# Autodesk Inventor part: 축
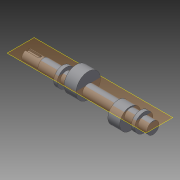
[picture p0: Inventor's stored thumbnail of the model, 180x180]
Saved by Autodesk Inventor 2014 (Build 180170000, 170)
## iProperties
Created: 2014-12
Part Number: 축
Material: 일반
Document SubType Name: Modeling
Designer: Owner
Density: 1 g/cm^3
Appearance: 기본값
Author: Owner
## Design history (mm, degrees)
sketch "스케치1"
  geometry: L1 (-90, 0)-(90, 0); L2 (-90, 0)-(-90, 7.5); L3 (-90, 7.5)-(-66, 7.5); L4 (-66, 7.5)-(-66, 8.5); L5 (-66, 8.5)-(-39, 8.5); L6 (-39, 8.5)-(-39, 13); L7 (-39, 13)-(-34, 13); L8 (-34, 13)-(-34, 8.5); L9 (-34, 8.5)-(72, 8.5); L10 (72, 8.5)-(72, 13); L11 (72, 13)-(77, 13); L12 (77, 13)-(77, 8.5); L13 (77, 8.5)-(90, 8.5); L14 (90, 8.5)-(90, 0); 7 further points
  constraints: 28 end point, 6 midpoint, 6 parallel, 4 perpendicular, 3 collinear, 3 horizontal alignment, 2 horizontal, 1 coincident
  dimensions: "d0" = 180 distance of L1.start L1.end; "d1" = 15 diameter of L3 L1; "d2" = 24 distance between parallel lines of L4 L2; "d3" = 32 distance between parallel lines of L4 L8; "d4" = 5 distance of L6.end L7.end; "d5" = 26 diameter of L7 L1; "d6" = 17 diameter of L5 L1; "d7" = 13 distance between parallel lines of L14 L12
revolve "회전1" sketch "스케치1" stored, may be unused: angle "d8" = 90 deg
node "작업 평면1"
sketch "스케치2"
  geometry: C1 r 17.5 at (-6, 0); 1 further point
  constraints: 1 centre point, 1 horizontal alignment
  dimensions: "d10" = 35 diameter of C1; "d11" = 6 distance of point (0, 0) C1.centre
extrude "돌출1" join sketch "스케치2" distance "d12" = 17; taper "d13" = 0 deg
node "작업 평면2"
sketch "스케치3"
  geometry: C1 r 15 at (-5, 0); 1 further point
  constraints: 1 centre point, 1 horizontal alignment
  dimensions: "d15" = 30 diameter of C1; "d16" = 5 distance of C1.centre point (0, 0)
extrude "돌출2" join sketch "스케치3" distance "d17" = 17; taper "d18" = 0 deg
node "작업 평면3"
sketch "스케치4"
  geometry: L1 (-12, -7.5)-(-12, 7.5) reference; L2 (-12, 2.5)-(5.5, 2.5); L3 (-12, -2.5)-(5.5, -2.5); A1 r 2.5 centre (5.5, 0) between (5.5, -2.5) and (5.5, 2.5); 3 further points
  constraints: 4 end point, 3 point on circle, 2 point on line, 2 tangent, 1 centre point, 1 horizontal alignment, 1 midpoint, 1 parallel, 1 perpendicular
  dimensions: "d19" = 5 diameter of A1; "d20" = 20 dimension on A1 L1
extrude "돌출3" cut sketch "스케치4" distance "d21" = 3; taper "d22" = 0 deg
node "솔리드1"
other parameters: "d9" = 14.5, "d14" = 14.5
